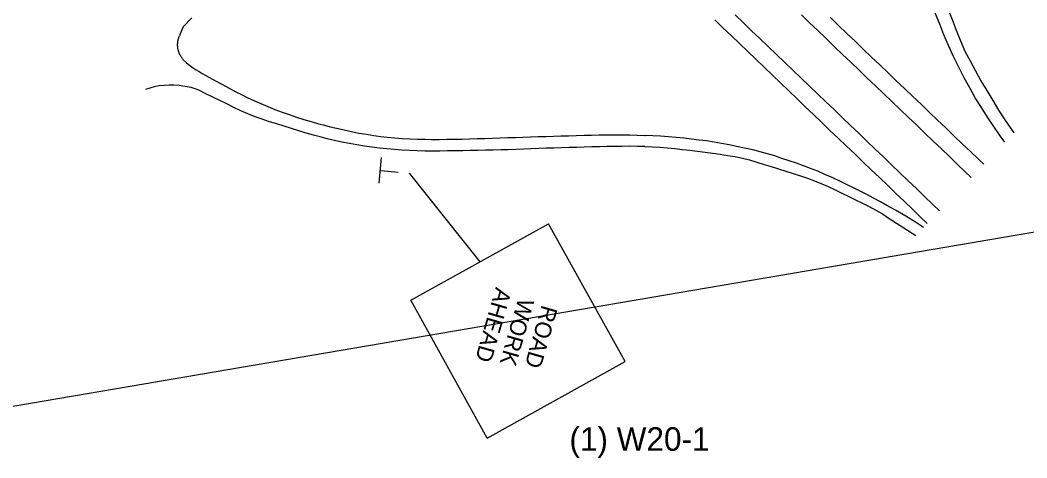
# Model space of a CAD drawing. Extents: x 1017892 to 1236694, y 658811 to 792468.
# Drawn here: x 1021371 to 1022033, y 659745 to 660033 of the extents above; entities that cross this region are included whole.
import ezdxf

# ---------------------------------------------------------------- set-up
doc = ezdxf.new("R2010")
doc.units = 0
for name, color, linetype in [('Level 3', 7, 'Continuous'), ('Level 8', 7, 'Continuous'), ('R_Border', 7, 'Continuous'), ('R_Proposed Road Annot', 7, 'Continuous'), ('S_EDGE_PAVEMENT', 7, 'Continuous')]:
    doc.layers.add(name, color=color, linetype=linetype)

msp = doc.modelspace()

# ---------------------------------------------------------------- linework, layer by layer
at = {"layer": 'Level 3'}
for p, q in [((1021607.35, 659925.48), (1021608.88, 659942.29)), ((1021608.36, 659933.82), (1021619.83, 659932.78))]:
    msp.add_line(p, q, dxfattribs=at)
at = {"layer": 'Level 8'}
for p, q in [((1021628.07, 659848.5), (1021718.64, 659898.82)), ((1021768.96, 659808.19), (1021718.64, 659898.82)), ((1021678.32, 659757.88), (1021628.07, 659848.5)), ((1021678.32, 659757.88), (1021768.96, 659808.19))]:
    msp.add_line(p, q, dxfattribs=at)
at = {"layer": 'R_Border'}
msp.add_lwpolyline([(1022921.74, 660121.31), (1022518.9, 659975.15), (1021256.99, 659760.06)], dxfattribs=at)
at = {"layer": 'R_Proposed Road Annot'}
msp.add_line((1021627.03, 659932.14), (1021673.36, 659873.66), dxfattribs=at)
at = {"layer": 'S_EDGE_PAVEMENT'}
for points in [[(1022018.59, 659952.41), (1022015.6, 659956.52), (1022011.4, 659962.74), (1022007.2, 659968.96), (1022003.22, 659975.32), (1021999.23, 659981.67), (1021995.56, 659988.22), (1021991.89, 659994.76), (1021988.36, 660001.85), (1021984.66, 660009.25), (1021981.6, 660016.11), (1021978.54, 660022.97), (1021975.83, 660029.96), (1021973.11, 660036.94), (1021970.7, 660044.05), (1021968.28, 660051.15), (1021966, 660059.16), (1021963.87, 660066.63), (1021962.06, 660073.91), (1021960.25, 660081.2), (1021958.86, 660088.57), (1021957.48, 660095.94), (1021956.26, 660103.35)], [(1021964.07, 660104.97), (1021965.55, 660097.62), (1021967.04, 660090.27), (1021968.53, 660082.92), (1021970.02, 660075.57), (1021971.51, 660068.22), (1021973.6, 660061.05), (1021975.66, 660054), (1021978.41, 660047.02), (1021981.16, 660040.05), (1021983.92, 660033.07), (1021986.75, 660026.12), (1021989.59, 660019.18), (1021992.43, 660012.23), (1021995.87, 660005.85), (1021999.37, 659999.37), (1022002.93, 659992.76), (1022006.8, 659986.33), (1022010.67, 659979.91), (1022014.54, 659973.49), (1022018.71, 659967.24), (1022024.49, 659958.6)], [(1021484.05, 660034.26), (1021478.43, 660028.34)], [(1021841.33, 660036.1), (1021846.74, 660030.92), (1021852.16, 660025.73), (1021857.58, 660020.54), (1021863, 660015.35), (1021868.42, 660010.16), (1021873.83, 660004.97), (1021879.25, 659999.79), (1021884.67, 659994.6), (1021890.08, 659989.41), (1021895.49, 659984.23), (1021900.91, 659979.04), (1021906.32, 659973.85), (1021911.74, 659968.66), (1021917.15, 659963.48), (1021922.57, 659958.29), (1021927.99, 659953.1), (1021933.4, 659947.91), (1021938.81, 659942.71), (1021944.22, 659937.52), (1021949.63, 659932.32), (1021955.05, 659927.11), (1021960.46, 659921.92), (1021965.86, 659916.72), (1021971.28, 659911.53), (1021975.65, 659907.33)], [(1021996.54, 659929.26), (1021987.81, 659937.62), (1021982.39, 659942.8), (1021976.97, 659947.98), (1021971.55, 659953.17), (1021966.13, 659958.35), (1021960.71, 659963.54), (1021955.29, 659968.72), (1021949.87, 659973.91), (1021944.45, 659979.09), (1021939.03, 659984.27), (1021933.61, 659989.46), (1021928.19, 659994.64), (1021922.77, 659999.83), (1021917.35, 660005.01), (1021911.93, 660010.2), (1021906.52, 660015.39), (1021901.11, 660020.59), (1021895.7, 660025.78), (1021890.28, 660030.97), (1021884.87, 660036.17)], [(1021903.93, 660034.37), (1021909.34, 660029.18), (1021914.76, 660023.99), (1021920.17, 660018.8), (1021925.59, 660013.62), (1021931.01, 660008.43), (1021936.43, 660003.25), (1021941.85, 659998.07), (1021947.27, 659992.88), (1021952.69, 659987.7), (1021958.11, 659982.52), (1021963.53, 659977.33), (1021968.95, 659972.15), (1021974.37, 659966.97), (1021979.79, 659961.78), (1021985.21, 659956.6), (1021990.63, 659951.42), (1021996.05, 659946.23), (1022001.47, 659941.05), (1022004.77, 659937.9)], [(1021478.43, 660028.34), (1021476.46, 660023.7), (1021476.01, 660022.42)], [(1021967.68, 659898.97), (1021963.26, 659903.21), (1021957.84, 659908.39), (1021952.43, 659913.58), (1021947.01, 659918.77), (1021941.61, 659923.95), (1021936.19, 659929.13), (1021930.77, 659934.31), (1021925.35, 659939.5), (1021919.93, 659944.68), (1021914.51, 659949.86), (1021909.09, 659955.04), (1021903.67, 659960.23), (1021898.25, 659965.41), (1021892.83, 659970.59), (1021887.42, 659975.79), (1021882, 659981), (1021876.6, 659986.19), (1021871.19, 659991.39), (1021865.78, 659996.59), (1021860.37, 660001.78), (1021854.97, 660006.98), (1021849.56, 660012.17), (1021844.15, 660017.37), (1021838.73, 660022.56), (1021833.31, 660027.74), (1021827.9, 660032.92)], [(1021478.7, 660006.43), (1021478.36, 660006.81), (1021478.02, 660007.2), (1021477.7, 660007.61), (1021477.39, 660008.03), (1021477.09, 660008.47), (1021476.81, 660008.92), (1021476.54, 660009.39), (1021476.29, 660009.86), (1021476.17, 660010.11), (1021476.06, 660010.35), (1021475.94, 660010.6), (1021475.84, 660010.85), (1021475.73, 660011.1), (1021475.64, 660011.36), (1021475.54, 660011.62), (1021475.45, 660011.88), (1021475.37, 660012.14), (1021475.29, 660012.41), (1021475.22, 660012.67), (1021475.15, 660012.94), (1021475.09, 660013.21), (1021475.03, 660013.48), (1021474.97, 660013.75), (1021474.92, 660014.02), (1021474.88, 660014.29), (1021474.84, 660014.57), (1021474.81, 660014.84), (1021474.78, 660015.12), (1021474.76, 660015.39), (1021474.74, 660015.67), (1021474.73, 660015.94), (1021474.72, 660016.22), (1021474.72, 660016.49), (1021474.73, 660016.77), (1021474.73, 660017.04), (1021474.75, 660017.32), (1021474.77, 660017.59), (1021474.79, 660017.86), (1021474.82, 660018.13), (1021474.85, 660018.4), (1021474.94, 660018.93), (1021475.04, 660019.46), (1021475.16, 660019.98), (1021475.29, 660020.49), (1021475.45, 660020.99), (1021475.62, 660021.48), (1021475.81, 660021.96), (1021476.01, 660022.42)], [(1021478.7, 660006.43), (1021480.62, 660004.71), (1021482.49, 660003.16), (1021484.62, 660001.57), (1021486.57, 660000.27), (1021488.79, 659998.88), (1021490.85, 659997.63), (1021493.17, 659996.31), (1021495.27, 659995.18), (1021497.76, 659993.79), (1021499.7, 659992.74), (1021504.13, 659990.29), (1021508.59, 659987.89), (1021513.11, 659985.57), (1021516.72, 659983.72), (1021520.37, 659981.93), (1021524.9, 659979.82), (1021529.49, 659977.82), (1021534.09, 659975.86), (1021538.73, 659974), (1021543.42, 659972.23), (1021548.16, 659970.58), (1021552.9, 659968.94), (1021557.7, 659967.42), (1021562.54, 659966.01), (1021567.37, 659964.59), (1021570.43, 659963.79), (1021574.39, 659962.78), (1021577.05, 659962.11), (1021579.26, 659961.59), (1021584.14, 659960.47), (1021589.03, 659959.4), (1021593.94, 659958.45), (1021598.87, 659957.65), (1021603.81, 659956.86), (1021608.27, 659956.24), (1021612.46, 659955.79), (1021617.45, 659955.34), (1021622.45, 659954.97), (1021627.44, 659954.68), (1021632.44, 659954.49), (1021637.43, 659954.37), (1021641.75, 659954.29), (1021646.7, 659954.26), (1021651.7, 659954.32), (1021656.71, 659954.39), (1021661.71, 659954.51), (1021666.71, 659954.65), (1021671.74, 659954.78), (1021676.81, 659954.95), (1021681.81, 659955.07), (1021686.81, 659955.26), (1021691.81, 659955.42), (1021696.8, 659955.6), (1021701.8, 659955.79), (1021706.8, 659955.95), (1021711.8, 659956.11), (1021716.8, 659956.27), (1021721.79, 659956.42), (1021726.79, 659956.59), (1021731.79, 659956.71), (1021736.87, 659956.9), (1021741.98, 659956.97), (1021746.97, 659957.08), (1021751.97, 659957.18), (1021756.97, 659957.26), (1021761.97, 659957.35), (1021766.97, 659957.32), (1021771.97, 659957.26), (1021776.98, 659957.14), (1021781.98, 659956.94), (1021782.2, 659956.93)], [(1021544.8, 659963.02), (1021539.96, 659964.43), (1021535.14, 659965.91), (1021530.36, 659967.47), (1021525.64, 659969.16), (1021520.98, 659970.98), (1021516.39, 659972.97), (1021511.65, 659975.15), (1021507.02, 659977.64), (1021502.39, 659979.82), (1021497.85, 659982.12), (1021493.2, 659984.27), (1021488.65, 659986.55), (1021486.21, 659987.55), (1021483.69, 659988.31), (1021481.05, 659988.85), (1021478.17, 659989.33), (1021475.74, 659989.62), (1021472.27, 659989.86), (1021469.36, 659989.93), (1021465.99, 659989.77), (1021462.67, 659989.4), (1021459.22, 659988.75), (1021456.51, 659988.01), (1021453.71, 659987.11)], [(1021781.87, 659949.56), (1021777.08, 659949.68), (1021772.08, 659949.78), (1021767.08, 659949.69), (1021762.08, 659949.63), (1021757.08, 659949.54), (1021752.08, 659949.47), (1021747.08, 659949.35), (1021742.08, 659949.2), (1021737.11, 659949.05), (1021732.14, 659948.91), (1021727.15, 659948.73), (1021722.15, 659948.56), (1021717.15, 659948.4), (1021712.15, 659948.23), (1021707.16, 659948.05), (1021702.16, 659947.86), (1021697.16, 659947.67), (1021692.17, 659947.51), (1021687.17, 659947.36), (1021682.17, 659947.23), (1021677.17, 659947.14), (1021672.18, 659947), (1021667.18, 659946.89), (1021662.18, 659946.81), (1021657.17, 659946.75), (1021652.17, 659946.68), (1021647.16, 659946.63), (1021642.16, 659946.56), (1021637.21, 659946.63), (1021632.21, 659946.75), (1021627.22, 659947.03), (1021622.22, 659947.2), (1021617.23, 659947.61), (1021612.24, 659948.01), (1021607.4, 659948.57), (1021602.53, 659949.19), (1021597.57, 659949.87), (1021592.64, 659950.68), (1021587.73, 659951.64), (1021582.81, 659952.53), (1021577.92, 659953.59), (1021573.04, 659954.74), (1021568.4, 659955.88), (1021564.04, 659957.06), (1021559.19, 659958.47), (1021554.35, 659959.89), (1021549.56, 659961.42), (1021544.8, 659963.02)], [(1021965.23, 659896.4), (1021959.94, 659899.76), (1021953.47, 659903.86), (1021946.74, 659907.67), (1021941.15, 659910.84), (1021936.8, 659913.31), (1021932.38, 659915.64), (1021927.96, 659917.98), (1021923.53, 659920.31), (1021919.04, 659922.51), (1021914.55, 659924.71), (1021910.06, 659926.91), (1021905.47, 659928.95), (1021900.21, 659931.29), (1021895.61, 659933.33), (1021890.93, 659935.12), (1021886.26, 659936.91), (1021881.58, 659938.7), (1021876.83, 659940.25), (1021872.07, 659941.8), (1021867.32, 659943.36), (1021862.5, 659944.69), (1021857.68, 659946.03), (1021852.86, 659947.37), (1021847.39, 659948.54), (1021842.21, 659949.65), (1021837.3, 659950.7), (1021832.37, 659951.55), (1021827.44, 659952.39), (1021822.51, 659953.24), (1021817.55, 659953.85), (1021812.59, 659954.46), (1021807.62, 659955.07), (1021802.64, 659955.51), (1021797.44, 659955.96), (1021792.18, 659956.42), (1021787.19, 659956.67), (1021782.2, 659956.93)], [(1021781.87, 659949.56), (1021786.87, 659949.32), (1021791.86, 659949.08), (1021796.74, 659948.63), (1021801.64, 659948.18), (1021806.63, 659947.72), (1021811.61, 659947.26), (1021816.56, 659946.56), (1021821.51, 659945.85), (1021826.46, 659945.15), (1021831.41, 659944.46), (1021836.37, 659943.78), (1021841.32, 659943.1), (1021846.11, 659941.95), (1021850.79, 659940.81), (1021855.56, 659939.33), (1021860.34, 659937.84), (1021865.11, 659936.36), (1021869.88, 659934.87), (1021874.66, 659933.38), (1021879.42, 659931.86), (1021884.18, 659930.33), (1021888.94, 659928.8), (1021893.59, 659926.92), (1021898.24, 659925.05), (1021902.56, 659923.31), (1021907.06, 659921.15), (1021911.57, 659918.98), (1021916.08, 659916.82), (1021920.55, 659914.56), (1021925.01, 659912.31), (1021929.47, 659910.05), (1021933.85, 659907.64), (1021938.24, 659905.24), (1021942.03, 659902.79), (1021960.19, 659891.11)]]:
    msp.add_lwpolyline(points, dxfattribs=at)

# ---------------------------------------------------------------- texts
at = {"layer": 'Level 8'}
for s, height, rotation, p in [('AHEAD', 10.799, 254.03457, (1021683.98, 659857.48)), ('WORK', 10.799, 254.03404, (1021698.83, 659850.5)), ('ROAD', 10.799, 254.03445, (1021714.34, 659845.84)), ('(1) W20-1', 15.5, 360, (1021732.35, 659749.51))]:
    msp.add_text(s, height=height, rotation=rotation, dxfattribs=at).set_placement(p)

doc.saveas('drawing.dxf')
